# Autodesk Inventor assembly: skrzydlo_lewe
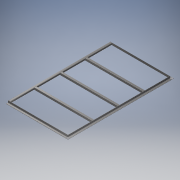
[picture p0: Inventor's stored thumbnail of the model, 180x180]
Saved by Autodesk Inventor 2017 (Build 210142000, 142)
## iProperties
Created: 2020-07
Part Number: skrzydlo_lewe
Document SubType Name: Assembly
Designer: X
_SolveAssemblyDoc: Frame Generator Solve Assembly
_Version: 15.0.0
Author: X
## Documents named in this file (3)
- C:\Users\WindowsX\Desktop\brama\skrzydlo_lewe.iam
- C:\Users\WindowsX\Desktop\brama\skrzydlo bramy.ipt
- C:\Users\WindowsX\Desktop\brama\skrzydlo_lewe\Frame\Frame0001.iam
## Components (3 placed, 2 different names)
1. skrzydlo bramy:1 — Zestawiający:1, Zestawiający:2, Zestawiający:3
2. Frame0001:1 [sub-assembly] — Zestawiający:1, Zestawiający:2, Zestawiający:3, Zestawiający:4, Zestawiający:5
3. skrzydlo bramy:2 — Zestawiający:4, Zestawiający:5
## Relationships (5: Mate 5)
- Zestawiający:1 [Mate]: skrzydlo bramy:1 ↔ Frame0001:1
- Zestawiający:2 [Mate]: skrzydlo bramy:1 ↔ Frame0001:1
- Zestawiający:3 [Mate]: skrzydlo bramy:1 ↔ Frame0001:1
- Zestawiający:4 [Mate]: Frame0001:1 ↔ skrzydlo bramy:2
- Zestawiający:5 [Mate]: Frame0001:1 ↔ skrzydlo bramy:2
